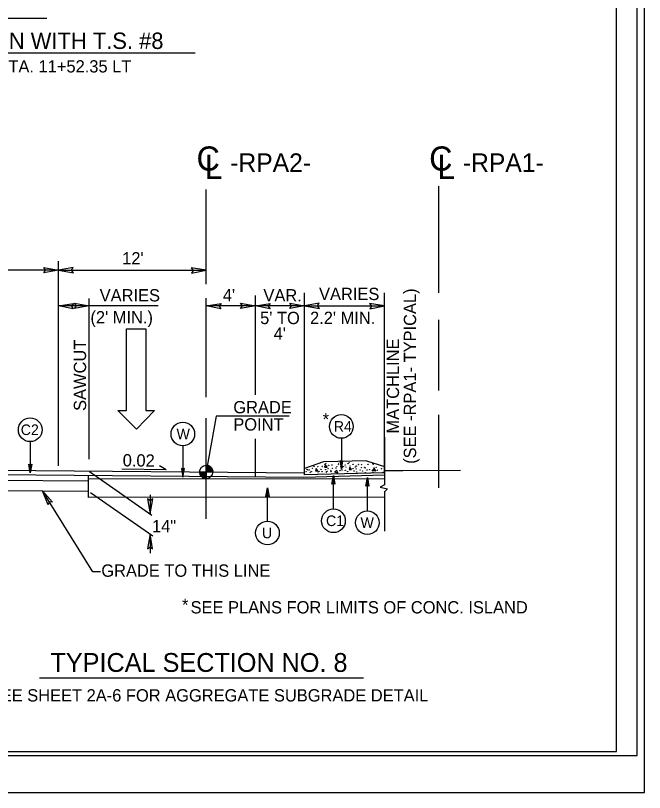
# Model space of a CAD drawing. Extents: x 573748 to 574632, y -54663 to -53209.
# Drawn here: x 574204.3 to 574281, y -54133.7 to -54038.9 of the extents above; entities that cross this region are included whole.
import ezdxf

# ---------------------------------------------------------------- set-up
doc = ezdxf.new("R2010")
doc.units = 0
for name, color, linetype in [('Prop Dimension', 7, 'Continuous'), ('Prop Dimension Text', 7, 'Continuous'), ('Prop Lane Arrow CELL', 7, 'Continuous'), ('Prop Terminator CELL', 7, 'Continuous'), ('Sheet Cutting Line CELL', 7, 'Continuous'), ('Sheet Plot Border Inside CELL', 7, 'Continuous'), ('Sheet Plot Border Outside CELL', 7, 'Continuous'), ('Sheet Typical CELL', 7, 'Continuous'), ('Typical Arrow Superelevation CELL', 7, 'Continuous'), ('Typical Curb CELL', 7, 'Continuous'), ('Typical Grade Point Symbol CELL', 7, 'Continuous'), ('Typical ID Circle CELL', 7, 'Continuous'), ('Typical Pavement Slope CELL', 7, 'Continuous'), ('Typical Terminator CELL', 7, 'Continuous'), ('Typical Text Centerline CELL', 7, 'Continuous'), ('Typical Text General CELL', 7, 'Continuous'), ('Typical Text ID Circle CELL', 7, 'Continuous'), ('Typical Text Label CELL', 7, 'Continuous')]:
    doc.layers.add(name, color=color, linetype=linetype)

# ---------------------------------------------------------------- blocks, each defined once
blk = doc.blocks.new('CENTERLINE TEXT CL')
at = {"layer": 'Typical Text Centerline CELL'}
blk.add_text('C', height=1.64, dxfattribs=at).set_placement((-0.546, -0.261))
blk.add_text('L', height=1.641, rotation=359.9469, dxfattribs=at).set_placement((-0.001, -0.821))

msp = doc.modelspace()

# ---------------------------------------------------------------- linework, layer by layer
at = {"layer": 'Prop Dimension'}
for p, q in [((574227.51, -54071.647), (574227.51, -54060.107)), ((574255.888, -54072.725), (574255.888, -54059.692)), ((574209.51, -54093.831), (574209.51, -54068.84)), ((574209.51, -54069.97), (574189.701, -54069.97)), ((574209.51, -54069.97), (574227.51, -54069.97)), ((574213.253, -54093.012), (574213.253, -54073.427)), ((574227.51, -54085.464), (574227.51, -54073.381)), ((574233.51, -54085.163), (574233.51, -54073.048)), ((574239.51, -54094.92), (574239.51, -54072.714)), ((574249.255, -54094.044), (574249.255, -54072.714)), ((574221.652, -54074.315), (574209.51, -54074.315)), ((574233.51, -54074.315), (574227.51, -54074.315)), ((574239.51, -54074.315), (574233.51, -54074.315)), ((574239.51, -54074.315), (574249.256, -54074.315)), ((574255.888, -54084.624), (574255.888, -54076.005)), ((574239.509, -54093.657), (574239.509, -54078.303)), ((574255.888, -54096.488), (574255.888, -54087.582)), ((574227.51, -54100.307), (574227.51, -54087.997)), ((574233.51, -54095.188), (574233.51, -54090.528)), ((574249.255, -54090.325), (574249.255, -54096.147)), ((574241.835, -54093.34), (574239.51, -54094.141)), ((574247.075, -54093.204), (574241.835, -54093.34)), ((574247.075, -54093.204), (574249.255, -54093.906)), ((574239.51, -54094.92), (574239.51, -54094.141)), ((574249.255, -54094.666), (574249.255, -54093.906)), ((574249.255, -54095.394), (574213.168, -54095.429)), ((574213.265, -54094.515), (574220.9, -54099.821)), ((574249.255, -54094.666), (574239.51, -54094.92)), ((574249.255, -54096.147), (574248.75, -54096.442)), ((574213.168, -54097.672), (574213.168, -54096.919)), ((574213.391, -54097.073), (574220.998, -54102.361)), ((574248.75, -54096.442), (574249.615, -54096.64)), ((574249.615, -54096.64), (574249.255, -54096.99)), ((574249.255, -54096.99), (574249.255, -54101.787)), ((574249.255, -54097.637), (574213.168, -54097.672)), ((574220.67, -54097.352), (574220.67, -54099.662)), ((574220.67, -54102.133), (574220.67, -54104.488))]:
    msp.add_line(p, q, dxfattribs=at)
for points in [[(574237.636, -54087.779), (574228.733, -54087.779), (574227.51, -54094.566)], [(574214.627, -54106.751), (574213.672, -54106.751), (574207.545, -54096.872)]]:
    msp.add_lwpolyline(points, dxfattribs=at)
at = {"layer": 'Prop Lane Arrow CELL'}
for p, q in [((574217.796, -54087.091), (574217.796, -54077.116)), ((574217.796, -54077.116), (574220.147, -54077.116)), ((574220.147, -54077.116), (574220.147, -54087.091)), ((574219.007, -54089.335), (574216.727, -54087.091)), ((574216.727, -54087.091), (574217.796, -54087.091)), ((574221.216, -54087.091), (574219.007, -54089.335)), ((574220.147, -54087.091), (574221.216, -54087.091))]:
    msp.add_line(p, q, dxfattribs=at)
at = {"layer": 'Prop Terminator CELL'}
for points in [[(574207.713, -54069.637), (574209.51, -54069.97), (574207.695, -54070.267), (574207.929, -54069.949)], [(574211.306, -54069.637), (574209.51, -54069.97), (574211.324, -54070.267), (574211.09, -54069.949)], [(574225.713, -54070.303), (574227.51, -54069.97), (574225.695, -54069.673), (574225.929, -54069.99)], [(574211.306, -54074.648), (574209.51, -54074.315), (574211.324, -54074.018), (574211.09, -54074.335)], [(574211.457, -54073.982), (574213.253, -54074.315), (574211.439, -54074.612), (574211.673, -54074.295)], [(574229.306, -54074.648), (574227.51, -54074.315), (574229.324, -54074.018), (574229.09, -54074.335)], [(574231.713, -54073.982), (574233.51, -54074.315), (574231.695, -54074.612), (574231.929, -54074.295)], [(574235.306, -54074.648), (574233.51, -54074.315), (574235.324, -54074.018), (574235.09, -54074.335)], [(574237.713, -54073.982), (574239.51, -54074.315), (574237.695, -54074.612), (574237.929, -54074.295)], [(574241.306, -54073.982), (574239.51, -54074.315), (574241.324, -54074.612), (574241.09, -54074.295)], [(574247.46, -54074.648), (574249.256, -54074.315), (574247.441, -54074.018), (574247.676, -54074.335)], [(574208.217, -54098.571), (574207.545, -54096.872), (574208.76, -54098.251), (574208.367, -54098.222)], [(574220.36, -54097.861), (574220.67, -54099.662), (574220.99, -54097.851), (574220.67, -54098.081)], [(574220.98, -54103.933), (574220.67, -54102.133), (574220.35, -54103.943), (574220.67, -54103.713)]]:
    msp.add_lwpolyline(points, close=True, dxfattribs=at)
at = {"layer": 'Sheet Cutting Line CELL'}
msp.add_line((573944.171, -54133.672), (574280.971, -54133.672), dxfattribs=at)
at = {"layer": 'Sheet Plot Border Inside CELL'}
msp.add_lwpolyline([(574280.071, -53918.162), (573946.771, -53918.162), (573946.771, -54129.182), (574280.071, -54129.182)], close=True, dxfattribs=at)
at = {"layer": 'Sheet Plot Border Outside CELL'}
msp.add_lwpolyline([(574280.971, -53913.672), (573944.171, -53913.672), (573944.171, -54133.672), (574280.971, -54133.672)], close=True, dxfattribs=at)
at = {"layer": 'Sheet Typical CELL'}
msp.add_lwpolyline([(574277.571, -53918.672), (573977.571, -53918.672), (573977.571, -54128.672), (574277.571, -54128.672)], close=True, dxfattribs=at)
at = {"layer": 'Typical Arrow Superelevation CELL'}
for q in [(574217.227, -54094.228), (574221.835, -54093.828)]:
    msp.add_line((574222.621, -54094.295), q, dxfattribs=at)
at = {"layer": 'Typical Curb CELL'}
for p, q in [((574240.922, -54094.16), (574240.831, -54094.431)), ((574240.831, -54094.431), (574241.132, -54094.45)), ((574241.132, -54094.45), (574240.922, -54094.16)), ((574242.054, -54093.708), (574241.963, -54093.979)), ((574241.963, -54093.979), (574242.264, -54093.998)), ((574242.264, -54093.998), (574242.054, -54093.708)), ((574243.435, -54094.395), (574243.174, -54094.572)), ((574243.585, -54094.672), (574243.435, -54094.395)), ((574243.978, -54093.682), (574243.886, -54093.954)), ((574243.886, -54093.954), (574244.187, -54093.973)), ((574244.187, -54093.973), (574243.978, -54093.682)), ((574245.031, -54093.98), (574244.94, -54094.251)), ((574244.94, -54094.251), (574245.241, -54094.27)), ((574245.241, -54094.27), (574245.031, -54093.98)), ((574248.06, -54094.171), (574247.799, -54094.348)), ((574247.799, -54094.348), (574248.21, -54094.448)), ((574248.21, -54094.448), (574248.06, -54094.171)), ((574243.174, -54094.572), (574243.585, -54094.672))]:
    msp.add_line(p, q, dxfattribs=at)
for centre in [(574242.111, -54093.532), (574243.612, -54093.537), (574244.941, -54093.455), (574247.84, -54093.541), (574239.81, -54094.241), (574239.933, -54094.316), (574240.122, -54094.313), (574240.497, -54094.112), (574240.654, -54093.884), (574241.008, -54093.66), (574241.125, -54093.919), (574241.282, -54094.483), (574241.505, -54094.246), (574241.66, -54093.911), (574241.977, -54093.632), (574242.073, -54094.285), (574242.388, -54094.143), (574242.458, -54093.754), (574242.719, -54094.384), (574242.849, -54093.732), (574242.921, -54094.126), (574243.349, -54094.09), (574243.447, -54093.866), (574243.667, -54093.624), (574243.836, -54094.421), (574244.077, -54094.313), (574244.258, -54093.91), (574244.454, -54093.702), (574244.481, -54094.373), (574244.548, -54093.985), (574244.807, -54093.555), (574245.036, -54093.823), (574245.43, -54093.647), (574245.432, -54094.166), (574245.533, -54094.458), (574245.696, -54093.974), (574245.807, -54094.212), (574245.816, -54093.833), (574246.095, -54093.656), (574246.282, -54094.315), (574246.453, -54093.692), (574246.461, -54094.039), (574246.573, -54094.442), (574246.831, -54094.014), (574246.886, -54094.101), (574247.139, -54094.338), (574247.237, -54093.646), (574247.425, -54094.276), (574247.759, -54094.415), (574247.895, -54093.627), (574247.976, -54094.083), (574248.262, -54094.021), (574248.371, -54094.353), (574248.893, -54094.185), (574239.687, -54094.516), (574240.198, -54094.618), (574240.339, -54094.538), (574241.14, -54094.637), (574241.632, -54094.537), (574242.149, -54094.591), (574242.29, -54094.51), (574242.745, -54094.536), (574244.775, -54094.526), (574245.866, -54094.57), (574246.922, -54094.655), (574247.49, -54094.695), (574249.076, -54094.605)]:
    msp.add_ellipse(centre, major_axis=(-0.0199, -0.002), ratio=0.961441, dxfattribs=at)
msp.add_ellipse((574247.852, -54094.595), major_axis=(0.0227, 0.0022), ratio=0.961441, start_param=0.356987, end_param=2.577098, dxfattribs=at)
at = {"layer": 'Typical Grade Point Symbol CELL'}
for p, q in [((574227.51, -54094.566), (574227.51, -54093.761)), ((574226.704, -54094.566), (574227.51, -54094.566)), ((574227.508, -54095.372), (574227.51, -54094.566)), ((574227.51, -54094.566), (574227.508, -54095.372)), ((574228.315, -54094.566), (574227.51, -54094.566))]:
    msp.add_line(p, q, dxfattribs=at)
for points in [[(574227.517, -54093.761), (574227.517, -54093.761), (574227.517, -54094.566)], [(574227.533, -54093.761), (574227.533, -54094.566)], [(574227.549, -54093.763), (574227.549, -54094.566)], [(574227.565, -54093.763), (574227.565, -54094.566)], [(574227.581, -54093.764), (574227.581, -54094.566)], [(574227.597, -54093.766), (574227.597, -54094.566)], [(574227.613, -54093.768), (574227.613, -54094.566)], [(574227.63, -54093.77), (574227.63, -54094.566)], [(574227.646, -54093.771), (574227.646, -54094.566)], [(574227.662, -54093.775), (574227.662, -54094.566)], [(574227.678, -54093.779), (574227.678, -54094.566)], [(574227.694, -54093.782), (574227.694, -54094.566)], [(574227.71, -54093.786), (574227.71, -54094.566)], [(574227.726, -54093.791), (574227.726, -54094.566)], [(574227.742, -54093.795), (574227.742, -54094.566)], [(574227.758, -54093.8), (574227.758, -54094.566)], [(574227.775, -54093.805), (574227.775, -54094.566)], [(574227.791, -54093.811), (574227.791, -54094.566)], [(574227.807, -54093.818), (574227.807, -54094.566)], [(574227.823, -54093.825), (574227.823, -54094.566)], [(574227.839, -54093.832), (574227.839, -54094.566)], [(574227.855, -54093.839), (574227.855, -54094.566)], [(574227.871, -54093.847), (574227.871, -54094.566)], [(574227.887, -54093.856), (574227.887, -54094.566)], [(574227.903, -54093.865), (574227.903, -54094.566)], [(574227.92, -54093.874), (574227.92, -54094.566)], [(574227.936, -54093.882), (574227.936, -54094.566)], [(574227.952, -54093.893), (574227.952, -54094.566)], [(574227.968, -54093.904), (574227.968, -54094.566)], [(574227.984, -54093.916), (574227.984, -54094.566)], [(574228, -54093.927), (574228, -54094.566)], [(574228.016, -54093.94), (574228.016, -54094.566)], [(574228.032, -54093.954), (574228.032, -54094.566)], [(574228.048, -54093.968), (574228.048, -54094.566)], [(574228.065, -54093.983), (574228.065, -54094.566)], [(574228.081, -54093.999), (574228.081, -54094.566)], [(574228.097, -54094.015), (574228.097, -54094.566)], [(574228.113, -54094.033), (574228.113, -54094.566)], [(574228.129, -54094.053), (574228.129, -54094.566)], [(574228.145, -54094.072), (574228.145, -54094.566)], [(574228.161, -54094.094), (574228.161, -54094.566)], [(574228.177, -54094.117), (574228.177, -54094.566)], [(574228.194, -54094.142), (574228.194, -54094.566)], [(574228.21, -54094.169), (574228.21, -54094.566)], [(574228.226, -54094.198), (574228.226, -54094.566)], [(574228.242, -54094.232), (574228.242, -54094.566)], [(574228.258, -54094.269), (574228.258, -54094.566)], [(574228.274, -54094.314), (574228.274, -54094.566)], [(574228.29, -54094.369), (574228.29, -54094.566)], [(574228.306, -54094.452), (574228.306, -54094.566)], [(574226.708, -54094.566), (574226.708, -54094.654)], [(574226.724, -54094.566), (574226.724, -54094.749)], [(574226.74, -54094.566), (574226.74, -54094.806)], [(574226.756, -54094.566), (574226.756, -54094.855)], [(574226.772, -54094.566), (574226.772, -54094.892)], [(574226.788, -54094.566), (574226.788, -54094.926)], [(574226.804, -54094.566), (574226.804, -54094.957)], [(574226.82, -54094.566), (574226.82, -54094.985)], [(574226.836, -54094.566), (574226.836, -54095.01)], [(574226.853, -54094.566), (574226.853, -54095.034)], [(574226.869, -54094.566), (574226.869, -54095.055)], [(574226.885, -54094.566), (574226.885, -54095.075)], [(574226.901, -54094.566), (574226.901, -54095.095)], [(574226.917, -54094.566), (574226.917, -54095.112)], [(574226.933, -54094.566), (574226.933, -54095.13)], [(574226.949, -54094.566), (574226.949, -54095.146)], [(574226.965, -54094.566), (574226.965, -54095.161)], [(574226.981, -54094.566), (574226.981, -54095.175)], [(574226.998, -54094.566), (574226.998, -54095.189)], [(574227.014, -54094.566), (574227.014, -54095.202)], [(574227.03, -54094.566), (574227.03, -54095.214)], [(574227.046, -54094.566), (574227.046, -54095.225)], [(574227.062, -54094.566), (574227.062, -54095.236)], [(574227.078, -54094.566), (574227.078, -54095.247)], [(574227.094, -54094.566), (574227.094, -54095.257)], [(574227.11, -54094.566), (574227.11, -54095.266)], [(574227.126, -54094.566), (574227.126, -54095.275)], [(574227.143, -54094.566), (574227.143, -54095.284)], [(574227.159, -54094.566), (574227.159, -54095.291)], [(574227.175, -54094.566), (574227.175, -54095.299)], [(574227.191, -54094.566), (574227.191, -54095.306)], [(574227.207, -54094.566), (574227.207, -54095.313)], [(574227.223, -54094.566), (574227.223, -54095.32)], [(574227.239, -54094.566), (574227.239, -54095.325)], [(574227.255, -54094.566), (574227.255, -54095.331)], [(574227.271, -54094.566), (574227.271, -54095.336)], [(574227.288, -54094.566), (574227.288, -54095.34)], [(574227.304, -54094.566), (574227.304, -54095.345)], [(574227.32, -54094.566), (574227.32, -54095.349)], [(574227.336, -54094.566), (574227.336, -54095.352)], [(574227.352, -54094.566), (574227.352, -54095.356)], [(574227.368, -54094.566), (574227.368, -54095.359)], [(574227.384, -54094.566), (574227.384, -54095.361)], [(574227.4, -54094.566), (574227.4, -54095.365)], [(574227.416, -54094.566), (574227.416, -54095.367)], [(574227.433, -54094.566), (574227.433, -54095.368)], [(574227.449, -54094.566), (574227.449, -54095.37)], [(574227.465, -54094.566), (574227.465, -54095.37)], [(574227.481, -54094.566), (574227.481, -54095.372)], [(574227.497, -54094.566), (574227.497, -54095.372), (574227.497, -54095.372)]]:
    msp.add_lwpolyline(points, dxfattribs=at)
msp.add_circle((574227.509, -54094.566), 0.806, dxfattribs=at)
for start, end in [(359.99048, 89.99048), (179.99048, 269.99048)]:
    msp.add_arc((574227.509, -54094.566), 0.806, start, end, dxfattribs=at)
at = {"layer": 'Typical ID Circle CELL'}
for p, q in [((574243.997, -54090.459), (574243.997, -54094.286)), ((574206.048, -54090.865), (574206.048, -54094.692)), ((574224.663, -54091.383), (574224.663, -54095.21)), ((574243.033, -54099.086), (574243.033, -54095.003)), ((574247.173, -54099.32), (574247.173, -54095.236)), ((574234.988, -54100.574), (574234.988, -54096.49))]:
    msp.add_line(p, q, dxfattribs=at)
for centre in [(574243.997, -54089.017), (574206.048, -54089.423), (574224.663, -54089.941), (574243.033, -54100.529), (574247.173, -54100.762), (574234.987, -54102.016)]:
    msp.add_circle(centre, 1.443, dxfattribs=at)
at = {"layer": 'Typical Pavement Slope CELL'}
for p, q in [((574193.744, -54094.288), (574239.51, -54094.665)), ((574251.518, -54094.436), (574249.255, -54094.451)), ((574258.521, -54094.389), (574251.518, -54094.436)), ((574193.744, -54094.817), (574239.437, -54095.194)), ((574213.168, -54096.919), (574213.168, -54094.977)), ((574239.437, -54095.194), (574249.255, -54094.938)), ((574193.744, -54095.492), (574213.168, -54095.652)), ((574178.625, -54096.634), (574213.168, -54096.919))]:
    msp.add_line(p, q, dxfattribs=at)
at = {"layer": 'Typical Terminator CELL'}
for points in [[(574243.815, -54093.231), (574243.997, -54094.286), (574244.184, -54093.225), (574243.997, -54093.36)], [(574206.229, -54093.637), (574206.048, -54094.692), (574205.86, -54093.631), (574206.048, -54093.766)], [(574224.481, -54094.155), (574224.663, -54095.21), (574224.85, -54094.149), (574224.663, -54094.284)], [(574242.851, -54096.057), (574243.033, -54095.003), (574243.22, -54096.063), (574243.033, -54095.929)], [(574246.991, -54096.291), (574247.173, -54095.236), (574247.36, -54096.296), (574247.173, -54096.162)], [(574234.806, -54097.545), (574234.988, -54096.49), (574235.175, -54097.551), (574234.988, -54097.416)]]:
    msp.add_lwpolyline(points, close=True, dxfattribs=at)
at = {"layer": 'Typical Text General CELL'}
msp.add_line((574226.168, -54043.461), (574175.728, -54043.461), dxfattribs=at)
at = {"layer": 'Typical Text Label CELL'}
for p, q in [((574208.061, -54039.229), (574194.675, -54039.229)), ((574207.175, -54119.684), (574246.686, -54119.684))]:
    msp.add_line(p, q, dxfattribs=at)

# ---------------------------------------------------------------- block references
at = {"layer": 'Prop Dimension', "xscale": 1.8000000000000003, "yscale": 1.8000000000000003}
for p in [(574227.313, -54057.338), (574255.691, -54057.338)]:
    msp.add_blockref('CENTERLINE TEXT CL', p, dxfattribs=at)

# ---------------------------------------------------------------- texts
at = {"layer": 'Prop Dimension'}
for s, height, p in [('-RPA2-', 2.25, (574230.441, -54057.955)), ('GRADE TO THIS LINE', 1.5, (574214.72, -54107.355))]:
    msp.add_text(s, height=height, dxfattribs=at).set_placement(p)
at = {"layer": 'Prop Dimension Text'}
for s, height, p in [('-RPA1-', 2.25, (574258.819, -54057.955)), ("12'", 1.5, (574217.265, -54069.254)), ('VARIES', 1.5, (574214.521, -54073.766)), ("4'", 1.5, (574229.537, -54073.766)), ('VAR.', 1.5, (574234.492, -54073.766)), ('VARIES', 1.5, (574241.279, -54073.6)), ("(2' MIN.)", 1.5, (574213.392, -54076.447)), ("5' TO", 1.5, (574234.091, -54076.531)), ("2.2' MIN.", 1.5, (574240.18, -54076.516)), ("4'", 1.5, (574235.747, -54078.43)), ('GRADE', 1.5, (574230.821, -54087.417)), ('*', 1.5, (574241.72, -54088.89)), ('POINT', 1.5, (574230.821, -54089.517)), ('14"', 1.5, (574220.9, -54101.926)), ('*', 1.5, (574224.565, -54111.539)), ('TYPICAL SECTION NO. 8', 2.3, (574208.517, -54118.964))]:
    msp.add_text(s, height=height, dxfattribs=at).set_placement(p)
for s, rotation, p in [('(SEE -RPA1- TYPICAL)', 90, (574253.118, -54093.58)), ('SAWCUT', 90, (574212.864, -54087.124)), ('MATCHLINE', 90, (574251.034, -54089.88)), ('0.02', 359.28447, (574217.323, -54093.886))]:
    msp.add_text(s, height=1.5, rotation=rotation, dxfattribs=at).set_placement(p)
at = {"layer": 'Typical Text General CELL'}
for s, height, p in [('USE IN CONJUNCTION WITH T.S. #8', 2, (574176.243, -54042.964)), ('-RPA2- STA. 10+00.00 TO STA. 11+52.35 LT', 1.5, (574177.576, -54045.835)), ('SEE PLANS FOR LIMITS OF CONC. ISLAND', 1.5, (574225.609, -54111.831)), ('SEE SHEET 2A-6 FOR AGGREGATE SUBGRADE DETAIL', 1.5, (574201.111, -54122.574))]:
    msp.add_text(s, height=height, dxfattribs=at).set_placement(p)
at = {"layer": 'Typical Text ID Circle CELL'}
for s, height, p in [('C2', 1.2912, (574204.89, -54090.065)), ('R4', 1.2912, (574243.074, -54089.66)), ('W', 1.291, (574223.895, -54090.584)), ('C1', 1.2912, (574242.129, -54101.172)), ('W', 1.291, (574246.338, -54101.405)), ('U', 1.291, (574234.317, -54102.659))]:
    msp.add_text(s, height=height, dxfattribs=at).set_placement(p)

doc.saveas('drawing.dxf')
